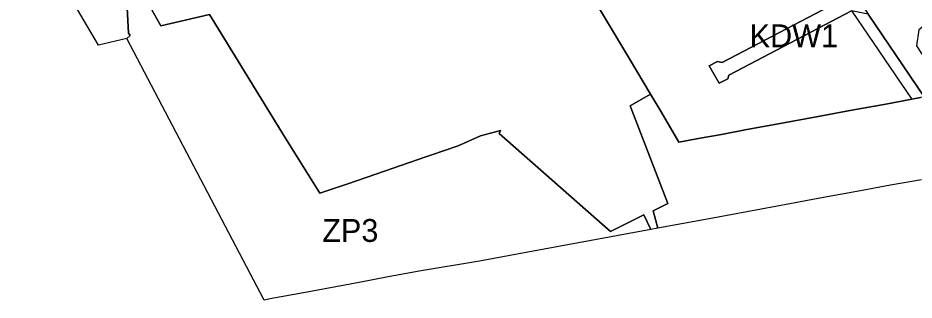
# Model space of a CAD drawing. Extents: x -284239 to -281592, y 34477 to 37267.
# Drawn here: x -284178.2 to -283786.7, y 34840.9 to 34964.3 of the extents above; entities that cross this region are included whole.
import ezdxf

# ---------------------------------------------------------------- set-up
doc = ezdxf.new("R2010")
doc.units = 0
for name, color, linetype in [('linie_rozgraniczajace', 7, 'Continuous'), ('linie_zabudowy_nieprzekraczalne', 7, 'Continuous'), ('oznaczenia_przeznaczen', 7, 'Continuous')]:
    doc.layers.add(name, color=color, linetype=linetype)

msp = doc.modelspace()

# ---------------------------------------------------------------- linework, layer by layer
at = {"layer": 'linie_rozgraniczajace'}
for points in [[(-284131.02, 34979.72), (-284129.86, 34957.6), (-284129.16, 34956.61), (-284130.65, 34955.32), (-284143.01, 34952.37), (-284178.17, 35012.4)], [(-283943, 35000), (-283911.001, 34946.396), (-283901.81, 34931), (-283910.72, 34925.87), (-283894.25, 34883.17), (-283900.6, 34879.94), (-283898.65, 34872.38), (-283901.71, 34871.82), (-283904.69, 34878.17), (-283919.27, 34870.96), (-283967.92, 34913.7), (-283967.3, 34915.07), (-283976.04, 34912.72), (-283985.78, 34908.32), (-283997.84, 34904.26), (-284000, 34903.5), (-284021.8, 34895.92), (-284034.04, 34891.77), (-284046.28, 34887.67), (-284061.56, 34912.17), (-284094.42, 34965.69), (-284115.75, 34960.83), (-284127.33, 34981.67)], [(-283806.652, 34965.834), (-283782.296, 34929.748), (-283783.905, 34929.454), (-283799.023, 34926.616), (-283813.822, 34923.937), (-283828.516, 34921.205), (-283845.172, 34918.155), (-283859.706, 34915.423), (-283870.846, 34913.354), (-283880.181, 34911.63), (-283889.464, 34909.88), (-283897.087, 34923.17), (-283897.116, 34923.218), (-283901.81, 34931), (-283911.001, 34946.396), (-283943, 35000)], [(-283733.394, 34998.539), (-283784.602, 34959.014), (-283785.619, 34952.082), (-283778.461, 34941.083), (-283771.976, 34931.636), (-283782.296, 34929.748), (-283806.652, 34965.834)], [(-284127.33, 34981.67), (-284115.75, 34960.83), (-284094.42, 34965.69), (-284061.56, 34912.17), (-284046.28, 34887.67), (-284034.04, 34891.77), (-284021.8, 34895.92), (-284000, 34903.5), (-283997.84, 34904.26), (-283985.78, 34908.32), (-283976.04, 34912.72), (-283967.3, 34915.07), (-283967.92, 34913.7), (-283919.27, 34870.96), (-283904.69, 34878.17), (-283901.71, 34871.82), (-283953.77, 34862.1), (-283976.57, 34857.97), (-284002.95, 34853.48), (-284016.37, 34851.03), (-284029.05, 34848.58), (-284053.48, 34844.1), (-284067.28, 34841.53), (-284070.54, 34840.9), (-284130.65, 34955.32), (-284129.16, 34956.61), (-284129.86, 34957.6), (-284131.02, 34979.72)], [(-283817.35, 34972.75), (-283870.556, 34944.722), (-283872.54, 34945.251), (-283876.244, 34943.267), (-283871.879, 34935.726), (-283868.042, 34937.578), (-283867.645, 34939.298), (-283814.052, 34967.365)], [(-283783.45, 34893.5), (-283796.94, 34891.16), (-283811.74, 34888.34), (-283826.17, 34885.76), (-283840.93, 34882.95), (-283872.22, 34877.15), (-283898.65, 34872.38), (-283900.6, 34879.94), (-283894.25, 34883.17), (-283910.72, 34925.87), (-283901.81, 34931), (-283897.116, 34923.218), (-283897.087, 34923.17), (-283889.464, 34909.88), (-283880.181, 34911.63), (-283870.846, 34913.354), (-283859.706, 34915.423), (-283845.172, 34918.155), (-283828.516, 34921.205), (-283813.822, 34923.937), (-283799.023, 34926.616), (-283783.905, 34929.454)]]:
    msp.add_lwpolyline(points, dxfattribs=at)
msp.add_lwpolyline([(-283876.244, 34943.267), (-283872.54, 34945.251), (-283870.556, 34944.722), (-283817.35, 34972.75), (-283815.901, 34979.537), (-283812.902, 34975.093), (-283809.348, 34969.828), (-283806.652, 34965.834), (-283813.935, 34967.344), (-283814.052, 34967.365), (-283867.645, 34939.298), (-283868.042, 34937.578), (-283871.879, 34935.726)], close=True, dxfattribs=at)
at = {"layer": 'linie_zabudowy_nieprzekraczalne'}
msp.add_lwpolyline([(-283787.711, 34928.949), (-283813.65, 34967.152)], dxfattribs=at)

# ---------------------------------------------------------------- texts
at = {"layer": 'oznaczenia_przeznaczen'}
for s, p in [('KDW1', (-283858.501, 34951.462)), ('ZP3', (-284045.22, 34866.334))]:
    msp.add_text(s, height=10, dxfattribs=at).set_placement(p)

doc.saveas('drawing.dxf')
